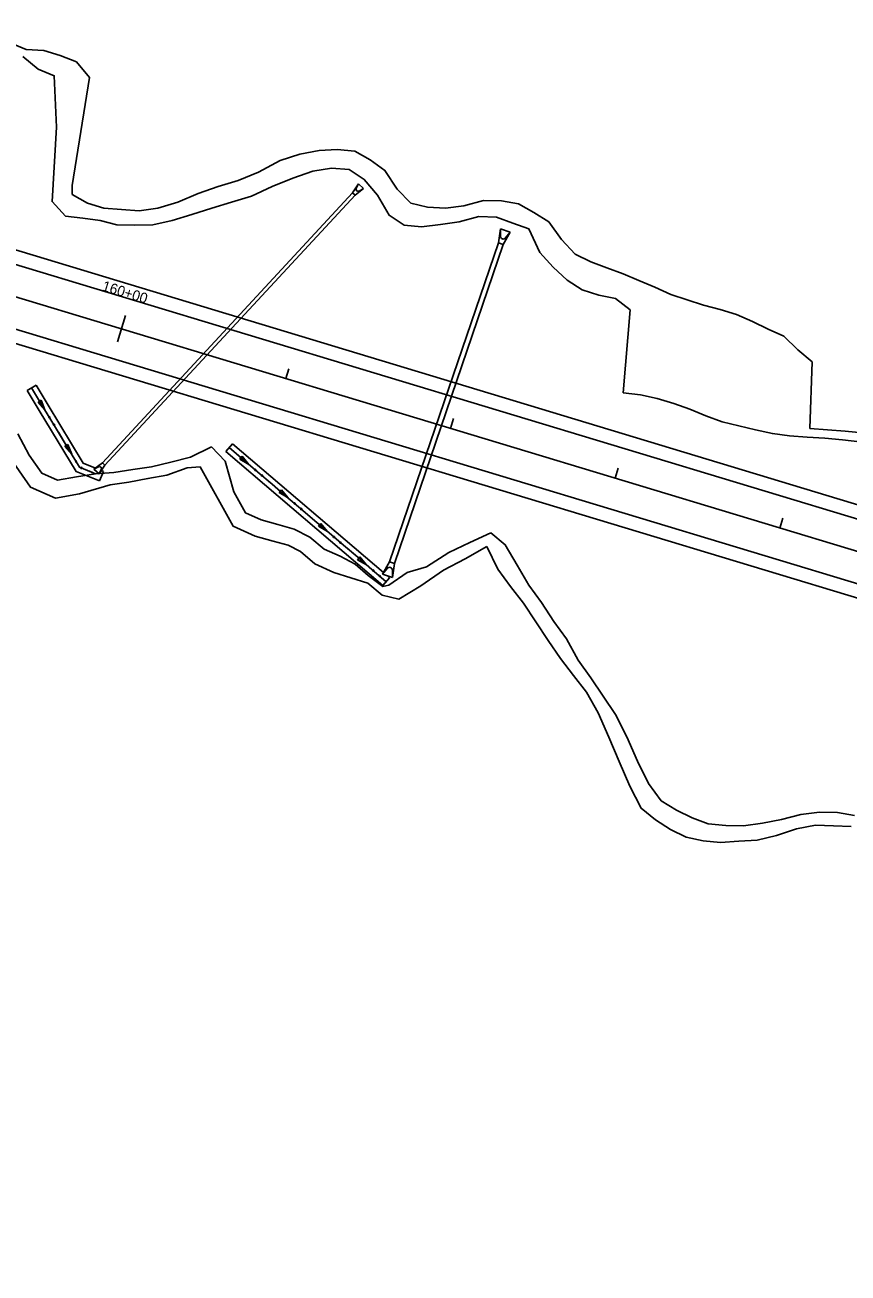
# Model space of a CAD drawing. Extents: x 979959 to 994833, y 1835619 to 1845316.
# Drawn here: x 981845 to 982323, y 1837782 to 1838507 of the extents above; entities that cross this region are included whole.
import ezdxf

# ---------------------------------------------------------------- set-up
doc = ezdxf.new("R2010")
doc.units = 0
for name, color, linetype in [('Future 5 Lane Construction Limits', 7, 'Continuous'), ('R_CONCRETE', 7, 'Continuous'), ('R_Drainage', 7, 'Continuous'), ('R_Horz Alg', 7, 'Continuous'), ('R_Horz Alg Stationing', 7, 'Continuous'), ('R_Proposed Const Limits', 7, 'Continuous'), ('R_Proposed Road', 7, 'Continuous'), ('R_Special Ditch', 7, 'Continuous')]:
    doc.layers.add(name, color=color, linetype=linetype)

msp = doc.modelspace()

# ---------------------------------------------------------------- linework, layer by layer
at = {"layer": 'Future 5 Lane Construction Limits'}
for points in [[(981836.28, 1838496.75), (981845.56, 1838492.89), (981855.8, 1838492.2), (981865.4, 1838489.4), (981874.74, 1838485.74), (981882.42, 1838476.58), (981872.29, 1838413.89), (981872.29, 1838413.86), (981872.3, 1838408.59), (981881.23, 1838403.57), (981890.76, 1838400.54), (981900.99, 1838399.81), (981911.19, 1838399.01), (981922.14, 1838400.67), (981933.65, 1838404.18), (981945.63, 1838409.24), (981957.26, 1838413.16), (981968.79, 1838416.74), (981980.69, 1838421.54), (981993.17, 1838428.27), (982004.77, 1838432.07), (982015.85, 1838434.15), (982026.48, 1838434.76), (982036.62, 1838433.72), (982045.55, 1838428.71), (982054.13, 1838422.54), (982061.29, 1838411.68), (982069.26, 1838403.47), (982079, 1838401.16), (982089.32, 1838400.71), (982100.15, 1838401.99), (982111.51, 1838405.02), (982121.93, 1838404.92), (982131.82, 1838403.07), (982140.76, 1838398.08), (982149.55, 1838392.61), (982156.91, 1838382.41), (982164.8, 1838373.97), (982173.88, 1838369.44), (982183.27, 1838365.95), (982192.65, 1838362.39), (982201.92, 1838358.51), (982211.19, 1838354.63), (982220.39, 1838350.49), (982229.87, 1838347.3), (982239.37, 1838344.17), (982249.09, 1838341.77), (982258.66, 1838338.86), (982267.84, 1838334.66), (982276.97, 1838330.32), (982286.15, 1838326.12), (982294.24, 1838318.32), (982302.55, 1838311.28), (982301.28, 1838272.53)], [(982301.28, 1838272.53), (982311.49, 1838271.76), (982321.73, 1838271.07), (982331.89, 1838270.1), (982342, 1838269), (982351.66, 1838266.39), (982361.27, 1838263.63), (982370.95, 1838261.1), (982380.62, 1838258.5), (982391.09, 1838258.6), (982401.27, 1838257.69), (982411.33, 1838256.41), (982420.66, 1838252.75), (982429.6, 1838247.75), (982438.53, 1838242.74), (982446.66, 1838235.07), (982454.71, 1838227.16)], [(981834.82, 1838257.37), (981848.04, 1838238.49), (981862.62, 1838232.12), (981876.65, 1838234.64), (981894.35, 1838239.73)], [(981894.35, 1838239.73), (981905.29, 1838241.38), (981916.36, 1838243.42), (981927.43, 1838245.49), (981939.15, 1838249.68), (981946.69, 1838250.33)], [(981946.69, 1838250.33), (981965.9, 1838215.79), (981978.79, 1838209.97), (981989.15, 1838207.06), (981997.86, 1838204.62), (982005.01, 1838201.03), (982013.49, 1838193.88), (982024.46, 1838188.9), (982044.18, 1838182.59)], [(982044.18, 1838182.59), (982052.59, 1838175.72), (982062.34, 1838173.39), (982075.12, 1838181.11), (982088.29, 1838190.13), (982100.77, 1838196.83), (982113.39, 1838204)], [(982113.39, 1838204), (982119.81, 1838190.71), (982127.24, 1838180.73), (982134.72, 1838170.92), (982141.89, 1838160.07), (982149.08, 1838149.31), (982156.33, 1838138.75), (982163.82, 1838128.97), (982171.34, 1838119.3), (982178.11, 1838107.13), (982184.3, 1838093.08), (982190.44, 1838078.84), (982196.6, 1838064.65), (982203.13, 1838051.71), (982211.54, 1838044.98), (982220.27, 1838039.3), (982229.41, 1838034.97), (982239.21, 1838032.82), (982249.35, 1838031.8), (982260.05, 1838032.65), (982270.69, 1838033.28), (982281.95, 1838035.97), (982293.56, 1838039.8), (982304.62, 1838041.84), (982314.97, 1838041.52), (982325.31, 1838041.16)]]:
    msp.add_lwpolyline(points, dxfattribs=at)
at = {"layer": 'R_CONCRETE'}
for p, q in [((981961.64, 1838259.12), (981965.54, 1838263.69)), ((981965.54, 1838263.69), (982053.39, 1838188.73)), ((981961.64, 1838259.12), (982052.99, 1838181.18)), ((982052.99, 1838181.18), (982056.88, 1838185.75)), ((982055.65, 1838186.8), (982056.88, 1838185.75))]:
    msp.add_line(p, q, dxfattribs=at)
at = {"layer": 'R_Drainage'}
for p, q in [((982035.36, 1838409.58), (982038.78, 1838414.75)), ((982038.78, 1838414.75), (982037.53, 1838412.09)), ((982038.78, 1838414.75), (982041.72, 1838412.03)), ((981889.87, 1838252.65), (982035.36, 1838409.58)), ((981891.34, 1838251.29), (982036.82, 1838408.22)), ((982035.36, 1838409.58), (982036.82, 1838408.22)), ((982036.82, 1838408.22), (982041.72, 1838412.03)), ((982041.72, 1838412.03), (982039.16, 1838410.58)), ((982121.38, 1838388.69), (982120.16, 1838380.49)), ((982127.05, 1838386.75), (982121.38, 1838388.69)), ((982121.39, 1838384.32), (982121.38, 1838388.69)), ((982123, 1838379.52), (982127.05, 1838386.75)), ((982124.37, 1838383.31), (982127.05, 1838386.75)), ((982056.9, 1838194.98), (982120.16, 1838380.49)), ((982059.74, 1838194.02), (982123, 1838379.52)), ((982123, 1838379.52), (982120.16, 1838380.49)), ((981851.3, 1838297.7), (981846.16, 1838294.6)), ((981889.87, 1838252.65), (981884.97, 1838248.84)), ((981889.87, 1838252.65), (981891.34, 1838251.29)), ((981884.97, 1838248.84), (981887.53, 1838250.29)), ((981884.97, 1838248.84), (981887.91, 1838246.12)), ((981891.34, 1838251.29), (981887.91, 1838246.12)), ((981887.91, 1838246.12), (981889.16, 1838248.78)), ((981888.28, 1838242.06), (981890.52, 1838247.62)), ((982052.85, 1838187.76), (982056.9, 1838194.98)), ((982059.74, 1838194.02), (982056.9, 1838194.98)), ((982055.52, 1838191.21), (982052.85, 1838187.76)), ((982058.53, 1838185.82), (982052.85, 1838187.76)), ((982058.5, 1838190.19), (982058.53, 1838185.82)), ((982059.74, 1838194.02), (982058.53, 1838185.82))]:
    msp.add_line(p, q, dxfattribs=at)
for points in [[(981851.3, 1838297.7), (981858.26, 1838286.17), (981878.62, 1838252.43), (981885.84, 1838249.51)], [(981846.16, 1838294.6), (981853.12, 1838283.07), (981874.52, 1838247.62), (981888.28, 1838242.06)], [(981889.25, 1838248.14), (981890.52, 1838247.62)]]:
    msp.add_lwpolyline(points, dxfattribs=at)
for centre, radius, start, end in [((982038.58, 1838411.59), 1.17, 154.69785, 299.638), ((982123.05, 1838384.33), 1.67, 180.21055, 322.1253), ((981888.11, 1838249.28), 1.17, 334.69785, 119.638), ((982056.84, 1838190.18), 1.67, 0.21054, 142.1253)]:
    msp.add_arc(centre, radius, start, end, dxfattribs=at)
at = {"layer": 'R_Horz Alg'}
msp.add_line((981399.33, 1838482.26), (983633.31, 1837806.41), dxfattribs=at)
at = {"layer": 'R_Horz Alg Stationing'}
for points in [[(981903.23, 1838338.17), (981898.6, 1838322.85)], [(981998.37, 1838307.3), (981996.63, 1838301.55)], [(982094.08, 1838278.34), (982092.35, 1838272.6)], [(982189.8, 1838249.38), (982188.06, 1838243.64)], [(982285.52, 1838220.43), (982283.78, 1838214.68)]]:
    msp.add_lwpolyline(points, dxfattribs=at)
at = {"layer": 'R_Proposed Const Limits'}
for p, q in [((981840.67, 1838269.51), (981847.32, 1838256.95)), ((981966.27, 1838235.71), (981961.24, 1838253.63)), ((981874.89, 1838244.48), (981885.88, 1838246.27)), ((982036.79, 1838193.7), (982044.47, 1838187.02))]:
    msp.add_line(p, q, dxfattribs=at)
for points in [[(981843.51, 1838488.81), (981852.54, 1838481.41), (981861.83, 1838477.6), (981863.27, 1838447.8), (981860.61, 1838404.49), (981868.47, 1838395.94), (981878.57, 1838394.78), (981888.59, 1838393.37), (981898.32, 1838391), (981908.71, 1838390.82), (981919.22, 1838391.02), (981930.4, 1838393.42), (981941.93, 1838397.01), (981953.45, 1838400.55), (981964.97, 1838404.1), (981976.5, 1838407.67), (981988.65, 1838413.32), (982000.53, 1838418.05), (982012.24, 1838422.23), (982023.19, 1838423.89), (982033.42, 1838423.16), (982042.11, 1838417.35), (982049.77, 1838408.14), (982056.7, 1838396.5), (982065.39, 1838390.69), (982075.53, 1838389.68), (982086.42, 1838391.13), (982097.31, 1838392.62), (982108.75, 1838395.88), (982119.07, 1838395.47), (982128.47, 1838391.99), (982137.87, 1838388.52), (982144.2, 1838374.94), (982152.02, 1838366.25), (982160.18, 1838358.68), (982168.93, 1838353.07), (982178.47, 1838350.08), (982188.33, 1838348.13), (982196.76, 1838341.45), (982192.64, 1838293.3)], [(981848.73, 1838296.15), (981855.69, 1838284.62), (981862.65, 1838273.09), (981869.61, 1838261.56), (981876.57, 1838250.03), (981885.88, 1838246.27)], [(982192.64, 1838293.3), (982202.72, 1838292.08), (982212.51, 1838289.93), (982222.11, 1838287.1), (982231.52, 1838283.7), (982240.8, 1838279.82), (982250.23, 1838276.47), (982259.97, 1838274.13), (982269.71, 1838271.78), (982279.5, 1838269.6), (982289.54, 1838268.26), (982299.75, 1838267.49), (982310.02, 1838266.9), (982320.17, 1838265.92), (982330.28, 1838264.78)], [(981864.23, 1838270.47), (981864.25, 1838270.43)], [(981885.88, 1838246.27), (981896.54, 1838246.98), (981907.49, 1838248.65), (981918.45, 1838250.33), (981929.7, 1838252.98), (981941.02, 1838255.86), (981953.28, 1838261.85)], [(981953.28, 1838261.85), (981961.24, 1838253.63)], [(981847.32, 1838256.95), (981854.61, 1838246.53), (981863.84, 1838242.5), (981874.89, 1838244.48)], [(981882.28, 1838247.72), (981882.32, 1838247.7)], [(981966.27, 1838235.71), (981973.03, 1838223.55), (981982.22, 1838219.4), (981991.85, 1838216.69), (982001.48, 1838213.99), (982010.55, 1838209.43), (982018.88, 1838202.42), (982028.06, 1838198.25), (982036.79, 1838193.7)], [(982044.47, 1838187.02), (982052.92, 1838180.7), (982056.44, 1838181.52), (982067.01, 1838188.84), (982078.42, 1838192.03), (982091.4, 1838200.41), (982103.64, 1838206.33), (982115.76, 1838211.84)], [(982115.76, 1838211.84), (982124.12, 1838204.96), (982131, 1838193.16), (982137.89, 1838181.41), (982145.29, 1838171.33), (982152.44, 1838160.41), (982159.78, 1838150.16), (982166.49, 1838137.79), (982173.84, 1838127.55), (982181.07, 1838116.92), (982188.3, 1838106.3), (982194.81, 1838093.28), (982201, 1838079.2), (982207.48, 1838066.08), (982214.91, 1838056.11), (982223.68, 1838050.57), (982232.81, 1838046.19), (982242.18, 1838042.64), (982252.35, 1838041.72), (982262.74, 1838041.54), (982273.65, 1838043.07), (982284.76, 1838045.25), (982296.04, 1838048.02), (982306.94, 1838049.52), (982317.31, 1838049.24), (982327.26, 1838047.6)]]:
    msp.add_lwpolyline(points, dxfattribs=at)
at = {"layer": 'R_Proposed Road'}
for p, q in [((981406.86, 1838507.14), (983640.84, 1837831.3)), ((981404.54, 1838499.48), (983638.52, 1837823.64)), ((981394.12, 1838465.03), (983628.1, 1837789.18)), ((981391.8, 1838457.37), (983625.78, 1837781.53))]:
    msp.add_line(p, q, dxfattribs=at)
at = {"layer": 'R_Special Ditch'}
for p, q in [((981854.29, 1838288.99), (981852.48, 1838287.9)), ((981856.48, 1838283.31), (981854.29, 1838288.99)), ((981852.48, 1838287.9), (981856.48, 1838283.31)), ((981869.81, 1838263.27), (981868, 1838262.18)), ((981868, 1838262.18), (981872, 1838257.59)), ((981872, 1838257.59), (981869.81, 1838263.27)), ((981971.12, 1838256.37), (981969.75, 1838254.76)), ((981969.75, 1838254.76), (981975, 1838251.67)), ((981975, 1838251.67), (981971.12, 1838256.37)), ((981993.97, 1838236.87), (981992.6, 1838235.26)), ((981992.6, 1838235.26), (981997.85, 1838232.17)), ((981997.85, 1838232.17), (981993.97, 1838236.87)), ((982016.82, 1838217.37), (982015.45, 1838215.76)), ((982020.7, 1838212.68), (982016.82, 1838217.37)), ((982015.45, 1838215.76), (982020.7, 1838212.68)), ((982039.67, 1838197.88), (982038.3, 1838196.27)), ((982038.3, 1838196.27), (982043.55, 1838193.18)), ((982043.55, 1838193.18), (982039.67, 1838197.88))]:
    msp.add_line(p, q, dxfattribs=at)
for points in [[(981848.73, 1838296.15), (981855.69, 1838284.62), (981856.48, 1838283.31)], [(981848.73, 1838296.15), (981855.69, 1838284.62), (981856.48, 1838283.31)], [(981864.25, 1838270.43), (981869.61, 1838261.56), (981872, 1838257.59)], [(981963.59, 1838261.41), (981980.2, 1838247.23), (981988.5, 1838240.15), (981996.81, 1838233.06), (982005.11, 1838225.98), (982013.41, 1838218.89), (982021.72, 1838211.81), (982030.02, 1838204.72), (982038.33, 1838197.64), (982046.63, 1838190.55), (982054.94, 1838183.47)], [(981963.59, 1838261.41), (981975, 1838251.67)], [(981882.32, 1838247.7), (981885.88, 1838246.27)], [(981986.41, 1838241.93), (981986.44, 1838241.91)], [(981986.44, 1838241.91), (981988.5, 1838240.15), (981996.81, 1838233.06), (981997.85, 1838232.17)], [(982009.26, 1838222.44), (982009.29, 1838222.41)], [(982009.29, 1838222.41), (982013.41, 1838218.89), (982020.7, 1838212.68)], [(982032.11, 1838202.94), (982032.14, 1838202.91)], [(982032.14, 1838202.91), (982038.33, 1838197.64), (982043.55, 1838193.18)]]:
    msp.add_lwpolyline(points, dxfattribs=at)
for centre in [(981859.1, 1838279.04), (981861.69, 1838274.75), (981874.62, 1838253.32), (981877.68, 1838249.62), (981978.83, 1838248.45), (981982.64, 1838245.2), (982001.68, 1838228.95), (982005.49, 1838225.7), (982024.53, 1838209.45), (982028.34, 1838206.2), (982047.38, 1838189.96), (982051.2, 1838186.7)]:
    msp.add_circle(centre, 0.375, dxfattribs=at)

# ---------------------------------------------------------------- texts
at = {"layer": 'R_Horz Alg Stationing'}
msp.add_text('160+00', height=6, rotation=343.16792, dxfattribs=at).set_placement((981889.24, 1838352.85))

doc.saveas('drawing.dxf')
